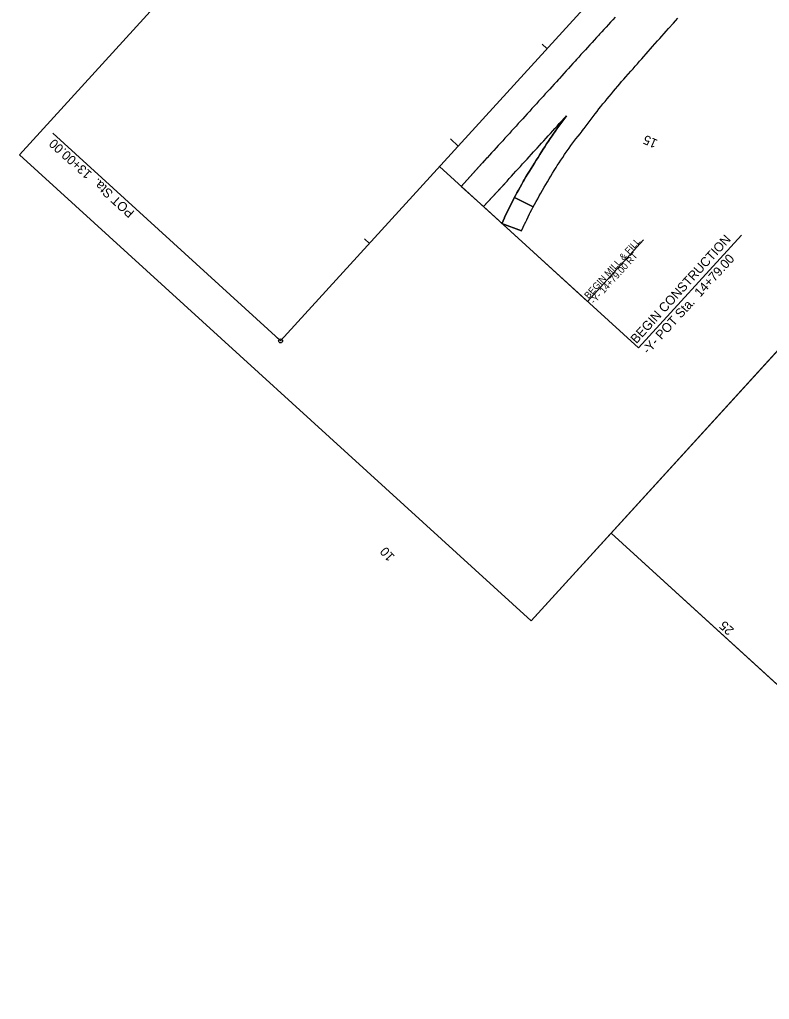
# Model space of a CAD drawing. Extents: x 1807040 to 1808827, y 913493 to 915218.
# Drawn here: x 1807040 to 1807609, y 913493 to 914236 of the extents above; entities that cross this region are included whole.
import ezdxf

# ---------------------------------------------------------------- set-up
doc = ezdxf.new("R2010")
doc.units = 0
for name, color, linetype in [('Old_Level_14', 7, 'Continuous'), ('Old_Level_18', 7, 'Continuous'), ('Prop Dimension', 7, 'Continuous'), ('Prop EOT', 7, 'Continuous'), ('Prop Horizontal Alignment Station Label', 7, 'Continuous'), ('Prop Horizontal Alignment Tick Label', 7, 'Continuous'), ('Prop Horizontal Alignment Tick Large', 7, 'Continuous'), ('Prop Horizontal Alignment Tick Small', 7, 'Continuous'), ('Scratch_Level_0', 7, 'Continuous'), ('Scratch_Level_1', 7, 'Continuous'), ('Scratch_Level_3', 7, 'Continuous')]:
    doc.layers.add(name, color=color, linetype=linetype)

msp = doc.modelspace()

# ---------------------------------------------------------------- linework, layer by layer
at = {"layer": 'Old_Level_14'}
msp.add_line((1807489.01, 913846.57), (1807877.03, 913492.93), dxfattribs=at)
at = {"layer": 'Old_Level_18'}
msp.add_line((1808438.77, 914888.63), (1807428.35, 913780.01), dxfattribs=at)
at = {"layer": 'Prop Dimension'}
for q in [(1807392.37, 914094.32), (1807513.69, 914069.07)]:
    msp.add_line((1807471.21, 914022.46), q, dxfattribs=at)
at = {"layer": 'Prop EOT'}
for p, q in [((1807392.46, 914094.24), (1807375.45, 914109.74)), ((1807420.99, 914075.98), (1807406.25, 914081.67)), ((1807406.29, 914081.65), (1807406.54, 914082.29))]:
    msp.add_line(p, q, dxfattribs=at)
for points in [[(1807492.05, 914237.98), (1807490.37, 914236.14), (1807488.68, 914234.29), (1807486.99, 914232.45), (1807485.31, 914230.6), (1807483.62, 914228.76), (1807481.93, 914226.91), (1807480.25, 914225.07), (1807479.68, 914224.44), (1807478, 914222.59), (1807476.32, 914220.74), (1807474.64, 914218.89), (1807472.96, 914217.04), (1807471.28, 914215.19), (1807469.6, 914213.34), (1807467.92, 914211.48), (1807466.24, 914209.63), (1807464.55, 914207.78), (1807462.87, 914205.93), (1807461.72, 914204.65), (1807460.04, 914202.8), (1807458.36, 914200.95), (1807456.69, 914199.09), (1807455.01, 914197.24), (1807453.33, 914195.38), (1807451.66, 914193.53), (1807449.98, 914191.67), (1807449.26, 914190.87), (1807447.57, 914189.03), (1807445.89, 914187.18), (1807444.21, 914185.33), (1807442.52, 914183.49), (1807440.84, 914181.64), (1807439.15, 914179.79), (1807437.47, 914177.94), (1807435.78, 914176.1), (1807434.1, 914174.25), (1807432.41, 914172.4), (1807430.73, 914170.55), (1807429.04, 914168.71), (1807427.36, 914166.86), (1807425.68, 914165.01), (1807425.38, 914164.69), (1807423.69, 914162.84), (1807422.01, 914161), (1807420.32, 914159.15), (1807418.63, 914157.3), (1807416.95, 914155.46), (1807415.26, 914153.61), (1807413.58, 914151.77), (1807411.89, 914149.92), (1807410.2, 914148.07), (1807408.52, 914146.23), (1807406.83, 914144.38), (1807405.14, 914142.54), (1807403.46, 914140.69), (1807401.77, 914138.85), (1807400.09, 914137), (1807398.4, 914135.15), (1807396.71, 914133.31), (1807395.03, 914131.46), (1807394.82, 914131.24), (1807393.15, 914129.38), (1807375.45, 914109.74)], [(1807420.99, 914075.98), (1807422.4, 914078.87), (1807423.21, 914080.55), (1807423.44, 914081.04), (1807424.28, 914082.81), (1807425.04, 914084.43), (1807426.16, 914086.66), (1807427.28, 914088.9), (1807427.52, 914089.36), (1807427.75, 914089.83), (1807428.84, 914092.08), (1807429.76, 914093.75), (1807430.98, 914095.93), (1807432.19, 914098.12), (1807433.4, 914100.31), (1807434.62, 914102.49), (1807435.83, 914104.68), (1807437.05, 914106.86), (1807438.26, 914109.05), (1807439.51, 914111.11), (1807440.81, 914113.25), (1807442.1, 914115.39), (1807443.4, 914117.52), (1807444.69, 914119.66), (1807445.99, 914121.8), (1807447.29, 914123.94), (1807448.26, 914125.43), (1807449.62, 914127.52), (1807450.99, 914129.62), (1807452.35, 914131.71), (1807453.72, 914133.81), (1807454.24, 914134.54), (1807455.71, 914136.57), (1807457.17, 914138.59), (1807458.63, 914140.62), (1807460.09, 914142.65), (1807461.55, 914144.68), (1807462.41, 914145.76), (1807463.97, 914147.71), (1807465.53, 914149.67), (1807467.08, 914151.62), (1807467.17, 914151.74), (1807468.69, 914153.72), (1807470.2, 914155.71), (1807471.72, 914157.7), (1807473.23, 914159.69), (1807473.92, 914160.61), (1807475.41, 914162.62), (1807476.91, 914164.62), (1807478.4, 914166.63), (1807479.89, 914168.63), (1807481.29, 914170.3), (1807482.89, 914172.22), (1807484.49, 914174.14), (1807486.09, 914176.06), (1807487.72, 914178.01), (1807489.32, 914179.93), (1807490.92, 914181.85), (1807492.52, 914183.77), (1807494.12, 914185.69), (1807495.72, 914187.61), (1807497.07, 914189.15), (1807498.72, 914191.02), (1807500.37, 914192.9), (1807502.03, 914194.77), (1807502.4, 914195.19), (1807504.05, 914197.07), (1807505.7, 914198.95), (1807507.34, 914200.83), (1807508.99, 914202.71), (1807510.64, 914204.59), (1807512.29, 914206.47), (1807513.94, 914208.34), (1807515.59, 914210.22), (1807517.24, 914212.1), (1807518.89, 914213.98), (1807520.54, 914215.86), (1807522.19, 914217.74), (1807522.6, 914218.2), (1807524.27, 914220.06), (1807525.94, 914221.92), (1807527.61, 914223.78), (1807529.28, 914225.65), (1807530.95, 914227.51), (1807532.62, 914229.37), (1807534.28, 914231.23), (1807534.71, 914231.7), (1807536.39, 914233.56), (1807538.06, 914235.41), (1807539.74, 914237.26)], [(1807429.95, 914094.09), (1807432.19, 914098.12), (1807433.4, 914100.31), (1807434.62, 914102.49), (1807435.83, 914104.68), (1807437.05, 914106.86), (1807438.26, 914109.05), (1807439.51, 914111.11), (1807440.81, 914113.25), (1807442.1, 914115.39), (1807443.4, 914117.52), (1807444.69, 914119.66), (1807445.99, 914121.8), (1807447.29, 914123.94), (1807448.26, 914125.43), (1807449.62, 914127.52), (1807450.99, 914129.62), (1807452.35, 914131.71), (1807453.72, 914133.81), (1807454.24, 914134.54), (1807455.71, 914136.57), (1807457.17, 914138.59), (1807458.63, 914140.62), (1807460.09, 914142.65), (1807461.55, 914144.68), (1807462.41, 914145.76), (1807463.97, 914147.71), (1807465.53, 914149.67), (1807467.08, 914151.62), (1807467.17, 914151.74), (1807468.69, 914153.72), (1807470.2, 914155.71), (1807471.72, 914157.7), (1807473.23, 914159.69), (1807473.92, 914160.61), (1807475.41, 914162.62), (1807476.91, 914164.62), (1807478.4, 914166.63), (1807479.89, 914168.63), (1807481.29, 914170.3), (1807482.89, 914172.22), (1807484.49, 914174.14), (1807486.09, 914176.06), (1807487.72, 914178.01), (1807489.32, 914179.93), (1807490.92, 914181.85), (1807492.52, 914183.77), (1807494.12, 914185.69), (1807495.72, 914187.61), (1807497.07, 914189.15), (1807498.72, 914191.02), (1807500.37, 914192.9), (1807502.03, 914194.77), (1807502.4, 914195.19), (1807504.05, 914197.07), (1807505.7, 914198.95), (1807507.34, 914200.83), (1807508.99, 914202.71), (1807510.64, 914204.59), (1807512.29, 914206.47), (1807513.94, 914208.34), (1807515.59, 914210.22), (1807517.24, 914212.1), (1807518.89, 914213.98), (1807520.54, 914215.86), (1807522.19, 914217.74), (1807522.6, 914218.2), (1807524.27, 914220.06), (1807525.94, 914221.92), (1807527.61, 914223.78), (1807529.28, 914225.65), (1807530.95, 914227.51), (1807532.62, 914229.37), (1807534.28, 914231.23), (1807534.71, 914231.7), (1807536.39, 914233.56), (1807538.06, 914235.41), (1807539.74, 914237.26)], [(1807392.36, 914094.33), (1807410.11, 914113.77), (1807411.79, 914115.62), (1807413.48, 914117.47), (1807415.16, 914119.31), (1807416.85, 914121.16), (1807418.53, 914123.01), (1807420.22, 914124.85), (1807421.9, 914126.7), (1807423.59, 914128.54), (1807425.28, 914130.39), (1807426.96, 914132.24), (1807428.65, 914134.08), (1807430.33, 914135.93), (1807431.28, 914136.97), (1807432.96, 914138.81), (1807434.65, 914140.66), (1807436.33, 914142.51), (1807438.01, 914144.36), (1807439.7, 914146.21), (1807441.38, 914148.05), (1807443.07, 914149.9), (1807444.75, 914151.75), (1807446.43, 914153.6), (1807448.12, 914155.44), (1807449.8, 914157.29), (1807455.25, 914163.27)], [(1807406.25, 914081.67), (1807407.13, 914083.62), (1807408.15, 914085.9), (1807408.33, 914086.29), (1807409.41, 914088.55), (1807410.48, 914090.8), (1807411.43, 914092.79), (1807412.57, 914095.01), (1807413.72, 914097.23), (1807414.86, 914099.46), (1807416.01, 914101.68), (1807416.45, 914102.53), (1807417.65, 914104.73), (1807418.85, 914106.92), (1807420.05, 914109.11), (1807421.25, 914111.31), (1807422.45, 914113.5), (1807423.16, 914114.79), (1807424.47, 914116.92), (1807425.78, 914119.05), (1807427.08, 914121.18), (1807428.33, 914123.21), (1807429.66, 914125.32), (1807430.99, 914127.44), (1807432.32, 914129.55), (1807433.66, 914131.67), (1807434.99, 914133.78), (1807436.32, 914135.9), (1807437.66, 914138.01), (1807438.77, 914139.78), (1807440.15, 914141.87), (1807441.52, 914143.96), (1807442.9, 914146.04), (1807444.27, 914148.13), (1807445.04, 914149.3), (1807446.52, 914151.32), (1807447.99, 914153.34), (1807449.47, 914155.36), (1807450.94, 914157.38), (1807452.27, 914159.2), (1807453.61, 914161.04), (1807454.83, 914162.75)], [(1807415.81, 914101.37), (1807417.65, 914104.73), (1807418.85, 914106.92), (1807420.05, 914109.11), (1807421.25, 914111.31), (1807422.45, 914113.5), (1807423.16, 914114.79), (1807424.47, 914116.92), (1807425.78, 914119.05), (1807427.08, 914121.18), (1807428.33, 914123.21), (1807429.66, 914125.32), (1807430.99, 914127.44), (1807432.32, 914129.55), (1807433.66, 914131.67), (1807434.99, 914133.78), (1807436.32, 914135.9), (1807437.66, 914138.01), (1807438.77, 914139.78), (1807440.15, 914141.87), (1807441.52, 914143.96), (1807442.9, 914146.04), (1807444.27, 914148.13), (1807445.04, 914149.3), (1807446.52, 914151.32), (1807447.99, 914153.34), (1807449.47, 914155.36), (1807455.25, 914163.27)]]:
    msp.add_lwpolyline(points, dxfattribs=at)
at = {"layer": 'Prop Horizontal Alignment Station Label'}
for p, q in [((1807237.23, 913993.53), (1807065.47, 914150.08)), ((1807509.92, 913987.18), (1807358.91, 914124.81)), ((1807509.92, 913987.18), (1807587.94, 914072.79))]:
    msp.add_line(p, q, dxfattribs=at)
msp.add_circle((1807238.34, 913992.52), 1.5, dxfattribs=at)
at = {"layer": 'Prop Horizontal Alignment Tick Large'}
msp.add_line((1807373.06, 914140.33), (1807367.15, 914145.72), dxfattribs=at)
at = {"layer": 'Prop Horizontal Alignment Tick Small'}
for p, q in [((1807440.42, 914214.24), (1807436.73, 914217.61)), ((1807305.7, 914066.42), (1807302, 914069.79)), ((1807238.34, 913992.52), (1807234.64, 913995.88))]:
    msp.add_line(p, q, dxfattribs=at)
at = {"layer": 'Scratch_Level_0'}
for p, q in [((1807480.48, 914225.32), (1807480.25, 914225.07)), ((1807375.45, 914109.74), (1807392.36, 914094.33)), ((1807414.86, 914099.46), (1807413.72, 914097.23)), ((1807415.84, 914101.36), (1807414.86, 914099.46)), ((1807415.81, 914101.37), (1807429.95, 914094.09)), ((1807429.95, 914094.09), (1807415.84, 914101.36)), ((1807411.43, 914092.79), (1807410.48, 914090.8)), ((1807407.13, 914083.62), (1807406.54, 914082.29)), ((1807427.52, 914089.36), (1807427.75, 914089.83)), ((1807406.29, 914081.65), (1807420.99, 914075.98)), ((1807420.99, 914075.98), (1807421.3, 914076.63)), ((1807423.21, 914080.55), (1807423.44, 914081.03)), ((1807423.44, 914081.03), (1807423.44, 914081.04))]:
    msp.add_line(p, q, dxfattribs=at)
for points in [[(1807492.05, 914237.98), (1807490.37, 914236.14), (1807488.68, 914234.29), (1807486.99, 914232.45), (1807485.31, 914230.6), (1807483.62, 914228.76), (1807481.93, 914226.91), (1807480.48, 914225.32)], [(1807507.34, 914200.83), (1807508.99, 914202.71), (1807510.64, 914204.59), (1807512.29, 914206.47), (1807513.94, 914208.34), (1807515.59, 914210.22), (1807517.24, 914212.1), (1807518.89, 914213.98), (1807520.54, 914215.86), (1807522.19, 914217.74), (1807522.6, 914218.2), (1807524.27, 914220.06), (1807525.94, 914221.92), (1807527.61, 914223.78), (1807529.28, 914225.65), (1807530.95, 914227.51), (1807532.62, 914229.37), (1807534.28, 914231.23), (1807534.71, 914231.7), (1807536.39, 914233.56), (1807538.06, 914235.41), (1807539.74, 914237.26)], [(1807480.25, 914225.07), (1807479.68, 914224.44), (1807478, 914222.59), (1807476.32, 914220.74), (1807474.64, 914218.89), (1807472.96, 914217.04), (1807471.28, 914215.19), (1807469.6, 914213.34), (1807467.92, 914211.48), (1807466.24, 914209.63), (1807464.55, 914207.78), (1807462.87, 914205.93), (1807461.72, 914204.65), (1807460.04, 914202.8), (1807458.36, 914200.95), (1807456.69, 914199.09), (1807455.01, 914197.24), (1807453.33, 914195.38), (1807451.66, 914193.53), (1807449.98, 914191.67), (1807449.26, 914190.87), (1807447.57, 914189.03), (1807445.89, 914187.18), (1807444.21, 914185.33), (1807442.52, 914183.49), (1807440.84, 914181.64), (1807439.15, 914179.79), (1807437.47, 914177.94), (1807435.78, 914176.1), (1807434.1, 914174.25), (1807432.41, 914172.4), (1807430.73, 914170.55), (1807429.04, 914168.71), (1807427.36, 914166.86), (1807425.68, 914165.01), (1807425.38, 914164.69), (1807423.69, 914162.84), (1807422.01, 914161), (1807420.32, 914159.15), (1807418.63, 914157.3), (1807416.95, 914155.46), (1807415.26, 914153.61), (1807413.58, 914151.77), (1807411.89, 914149.92), (1807410.2, 914148.07), (1807408.52, 914146.23), (1807406.83, 914144.38), (1807405.14, 914142.54), (1807403.46, 914140.69), (1807401.77, 914138.85), (1807400.09, 914137), (1807398.4, 914135.15), (1807396.71, 914133.31), (1807395.03, 914131.46), (1807394.82, 914131.24), (1807393.15, 914129.38), (1807391.48, 914127.53), (1807375.45, 914109.74)], [(1807429.95, 914094.09), (1807432.19, 914098.12), (1807433.4, 914100.31), (1807434.62, 914102.49), (1807435.83, 914104.68), (1807437.05, 914106.86), (1807438.26, 914109.05), (1807439.51, 914111.11), (1807440.81, 914113.25), (1807442.1, 914115.39), (1807443.4, 914117.52), (1807444.69, 914119.66), (1807445.99, 914121.8), (1807447.29, 914123.94), (1807448.26, 914125.43), (1807449.62, 914127.52), (1807450.99, 914129.62), (1807452.35, 914131.71), (1807453.72, 914133.81), (1807454.24, 914134.54), (1807455.71, 914136.57), (1807457.17, 914138.59), (1807458.63, 914140.62), (1807460.09, 914142.65), (1807461.55, 914144.68), (1807462.41, 914145.76), (1807463.97, 914147.71), (1807465.53, 914149.67), (1807467.08, 914151.62), (1807467.17, 914151.74), (1807468.69, 914153.72), (1807470.2, 914155.71), (1807471.72, 914157.7), (1807473.23, 914159.69), (1807473.92, 914160.61), (1807475.41, 914162.62), (1807476.91, 914164.62), (1807478.4, 914166.63), (1807479.89, 914168.63), (1807481.29, 914170.3), (1807482.89, 914172.22), (1807484.49, 914174.14), (1807486.09, 914176.06), (1807487.72, 914178.01), (1807489.32, 914179.93), (1807490.92, 914181.85), (1807492.52, 914183.77), (1807494.12, 914185.69), (1807495.72, 914187.61), (1807497.07, 914189.15), (1807498.72, 914191.02), (1807500.37, 914192.9), (1807502.03, 914194.77), (1807502.4, 914195.19), (1807504.05, 914197.07), (1807505.7, 914198.95), (1807507.34, 914200.83)], [(1807392.36, 914094.33), (1807408.42, 914111.93), (1807410.11, 914113.77), (1807411.79, 914115.62), (1807413.48, 914117.47), (1807415.16, 914119.31), (1807416.85, 914121.16), (1807418.53, 914123.01), (1807420.22, 914124.85), (1807421.9, 914126.7), (1807423.59, 914128.54), (1807425.28, 914130.39), (1807426.96, 914132.24), (1807428.65, 914134.08), (1807430.33, 914135.93), (1807431.28, 914136.97), (1807432.96, 914138.81), (1807434.65, 914140.66), (1807436.33, 914142.51), (1807438.01, 914144.36), (1807439.7, 914146.21), (1807441.38, 914148.05), (1807443.07, 914149.9), (1807444.75, 914151.75), (1807446.43, 914153.6), (1807448.12, 914155.44), (1807449.8, 914157.29), (1807455.25, 914163.27)], [(1807455.25, 914163.27), (1807449.47, 914155.36), (1807447.99, 914153.34), (1807446.52, 914151.32), (1807445.04, 914149.3), (1807444.27, 914148.13), (1807442.9, 914146.04), (1807441.52, 914143.96), (1807440.15, 914141.87), (1807438.77, 914139.78), (1807437.66, 914138.01), (1807436.32, 914135.9), (1807434.99, 914133.78), (1807433.66, 914131.67), (1807432.32, 914129.55), (1807430.99, 914127.44), (1807429.66, 914125.32), (1807428.33, 914123.21), (1807427.08, 914121.18), (1807425.78, 914119.05), (1807424.47, 914116.92), (1807423.16, 914114.79), (1807422.45, 914113.5), (1807421.25, 914111.31), (1807420.05, 914109.11), (1807418.85, 914106.92), (1807417.65, 914104.73), (1807415.81, 914101.37)], [(1807410.48, 914090.8), (1807409.41, 914088.55), (1807408.33, 914086.29)], [(1807413.72, 914097.23), (1807412.57, 914095.01), (1807411.43, 914092.79)], [(1807427.75, 914089.83), (1807428.84, 914092.08), (1807429.76, 914093.75), (1807429.95, 914094.09)], [(1807408.33, 914086.29), (1807408.15, 914085.9), (1807407.13, 914083.62)], [(1807423.44, 914081.04), (1807424.28, 914082.81), (1807425.04, 914084.43)], [(1807425.04, 914084.43), (1807426.16, 914086.66), (1807427.28, 914088.9), (1807427.52, 914089.36)], [(1807406.54, 914082.29), (1807406.52, 914082.26), (1807406.29, 914081.65)], [(1807421.3, 914076.63), (1807422.4, 914078.87), (1807423.21, 914080.55)], [(1807423.44, 914081.03), (1807423.44, 914081.03)]]:
    msp.add_lwpolyline(points, dxfattribs=at)
at = {"layer": 'Scratch_Level_1'}
for points in [[(1807040.33, 914133.66), (1807040.33, 914133.66), (1807428.35, 913780.01), (1808256.27, 914688.39), (1807868.25, 915042.04)], [(1807489.01, 913846.57), (1807877.03, 913492.93), (1808826.79, 914534.98), (1808438.77, 914888.63)]]:
    msp.add_lwpolyline(points, close=True, dxfattribs=at)
at = {"layer": 'Scratch_Level_3'}
msp.add_line((1807238.34, 913992.52), (1808046.68, 914879.41), dxfattribs=at)

# ---------------------------------------------------------------- texts
at = {"layer": 'Prop Dimension'}
for s, p in [('BEGIN MILL & FILL', (1807471.85, 914024.13)), ('-Y- 14+79.00 RT', (1807476.28, 914020.09))]:
    msp.add_text(s, height=5, rotation=47.65322, dxfattribs=at).set_placement(p)
at = {"layer": 'Prop Horizontal Alignment Station Label'}
for s, rotation, p in [('POT Sta.  13+00.00', 137.65322, (1807127.98, 914090.4)), ('BEGIN CONSTRUCTION', 47.65322, (1807508.25, 913989.95)), ('-Y- POT Sta.  14+79.00', 47.65322, (1807517.12, 913981.86))]:
    msp.add_text(s, height=7, rotation=rotation, dxfattribs=at).set_placement(p)
at = {"layer": 'Prop Horizontal Alignment Tick Label'}
for s, rotation, p in [('15', 156.2667, (1807524.91, 914144.7)), ('10', 132.29357, (1807325.27, 913829.14)), ('25', 137.65322, (1807582.8, 913773.68))]:
    msp.add_text(s, height=7, rotation=rotation, dxfattribs=at).set_placement(p)

doc.saveas('drawing.dxf')
